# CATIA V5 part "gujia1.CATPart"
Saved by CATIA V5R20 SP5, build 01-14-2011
Part number: 骨架1
Bounding box of the stored display mesh (mm): x -120 to 0, y -2.5 to 2.5, z 0 to 75
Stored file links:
  E:\180512116\zp\20190505\180512116赵克君\gujia1.CATPart
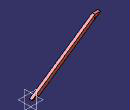
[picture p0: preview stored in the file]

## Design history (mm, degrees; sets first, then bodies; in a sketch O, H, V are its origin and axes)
Body1 (main body)
  Sketch1 on zx-plane, origin (0, 0, 0), H (-1, 0, 0), V (0, 0, 1)
    line L1 (0, 0) -> (3.9678, 0)
    point P2 (120, -75)
    line L2 (0, 0) -> (109.9975, 75)
    line L3 (10.9678, 0) -> (120, 75)
    point P4 (10.9678, 0)
    line L4 (109.9975, 75) -> (120, 75)
    arc A1 centre (7.4678, 0) radius 3.5 from (10.9678, 0) to (3.9678, 0) ccw
    point P5 (7.4678, 0)
    point P6 (10.9678, 0)
    radius A1 = 3.5
    horizontal: L1 H, L4 H
    coincidence: P4 H, P5 L1, A1 P6, P6 L3, P6 H
  Pad1: profile Sketch1, direction (0, 1, 0), length 2.5, mirrored extent
  Sketch2 on end face of Pad1, origin (0, 2.5, 0), H (-1, 0, 0), V (0, 0, 1)
    circle A1 centre (110.0194, 70.1344) radius 1.2589
  Pocket1: profile Sketch2, direction (0, -1, 0), length 10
